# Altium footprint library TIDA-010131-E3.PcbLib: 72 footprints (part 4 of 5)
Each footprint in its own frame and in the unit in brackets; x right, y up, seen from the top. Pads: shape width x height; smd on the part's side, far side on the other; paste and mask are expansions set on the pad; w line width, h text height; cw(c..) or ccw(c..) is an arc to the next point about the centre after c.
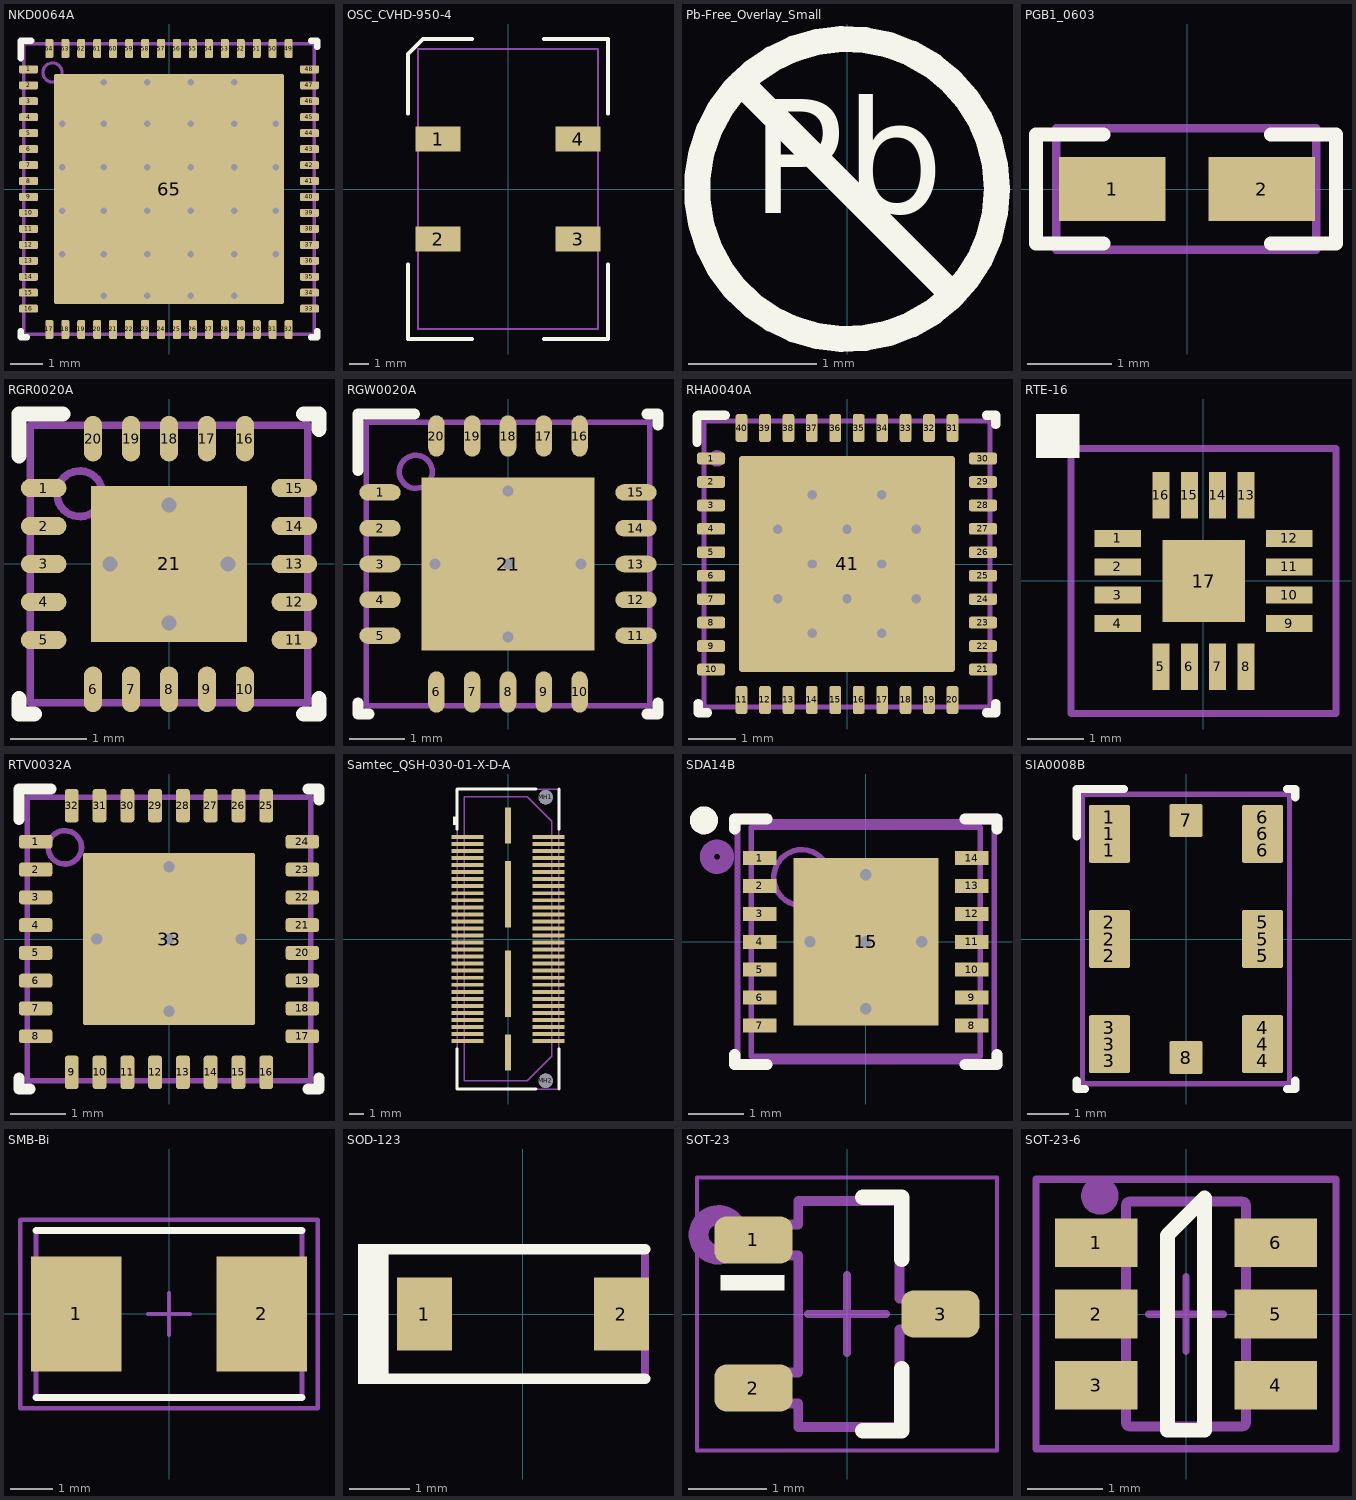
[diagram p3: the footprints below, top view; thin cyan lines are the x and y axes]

## NKD0064A [mm] "QFN, 64-Leads, Body 9x9mm, Pitch 0.5mm"
height 0.8
pads (65):
  rrect40% 0.6x0.25 smd: 1(-4.4,3.75) 2(-4.4,3.25) 3(-4.4,2.75) 4(-4.4,2.25) 5(-4.4,1.75) 6(-4.4,1.25) 7(-4.4,0.75) 8(-4.4,0.25) 9(-4.4,-0.25) 10(-4.4,-0.75) 11(-4.4,-1.25) 12(-4.4,-1.75) 13(-4.4,-2.25) 14(-4.4,-2.75) 15(-4.4,-3.25) 16(-4.4,-3.75) 33(4.4,-3.75) 34(4.4,-3.25) 35(4.4,-2.75) 36(4.4,-2.25) 37(4.4,-1.75) 38(4.4,-1.25) 39(4.4,-0.75) 40(4.4,-0.25) 41(4.4,0.25) 42(4.4,0.75) 43(4.4,1.25) 44(4.4,1.75) 45(4.4,2.25) 46(4.4,2.75) 47(4.4,3.25) 48(4.4,3.75)
  rrect40% 0.25x0.6 smd: 17(-3.75,-4.4) 18(-3.25,-4.4) 19(-2.75,-4.4) 20(-2.25,-4.4) 21(-1.75,-4.4) 22(-1.25,-4.4) 23(-0.75,-4.4) 24(-0.25,-4.4) 25(0.25,-4.4) 26(0.75,-4.4) 27(1.25,-4.4) 28(1.75,-4.4) 29(2.25,-4.4) 30(2.75,-4.4) 31(3.25,-4.4) 32(3.75,-4.4) 49(3.75,4.4) 50(3.25,4.4) 51(2.75,4.4) 52(2.25,4.4) 53(1.75,4.4) 54(1.25,4.4) 55(0.75,4.4) 56(0.25,4.4) 57(-0.25,4.4) 58(-0.75,4.4) 59(-1.25,4.4) 60(-1.75,4.4) 61(-2.25,4.4) 62(-2.75,4.4) 63(-3.25,4.4) 64(-3.75,4.4)
  rrect1% 7.2x7.2 smd paste-3.6: 65(0,0)
via 0.68,-3.35 diameter 0.5 hole 0.2
via -0.68,-3.35 diameter 0.5 hole 0.2
via 3.35,0.68 diameter 0.5 hole 0.2
via 3.35,2.04 diameter 0.5 hole 0.2
via -3.35,0.68 diameter 0.5 hole 0.2
via -3.35,2.04 diameter 0.5 hole 0.2
via -3.35,-0.68 diameter 0.5 hole 0.2
via -3.35,-2.04 diameter 0.5 hole 0.2
via 3.35,-2.04 diameter 0.5 hole 0.2
via 3.35,-0.68 diameter 0.5 hole 0.2
via -2.04,-3.35 diameter 0.5 hole 0.2
via 2.04,-3.35 diameter 0.5 hole 0.2
via 2.04,3.35 diameter 0.5 hole 0.2
via 0.68,3.35 diameter 0.5 hole 0.2
via -0.68,3.35 diameter 0.5 hole 0.2
via -2.04,3.35 diameter 0.5 hole 0.2
via 2.04,2.04 diameter 0.5 hole 0.2
via 0.68,2.04 diameter 0.5 hole 0.2
via -0.68,2.04 diameter 0.5 hole 0.2
via -2.04,2.04 diameter 0.5 hole 0.2
via 2.04,-2.04 diameter 0.5 hole 0.2
via 0.68,-2.04 diameter 0.5 hole 0.2
via -0.68,-2.04 diameter 0.5 hole 0.2
via -2.04,-2.04 diameter 0.5 hole 0.2
via -2.04,-0.68 diameter 0.5 hole 0.2
via 2.04,-0.68 diameter 0.5 hole 0.2
via 2.04,0.68 diameter 0.5 hole 0.2
via -2.04,0.68 diameter 0.5 hole 0.2
via 0.68,-0.68 diameter 0.5 hole 0.2
via -0.68,-0.68 diameter 0.5 hole 0.2
via -0.68,0.68 diameter 0.5 hole 0.2
via 0.68,0.68 diameter 0.5 hole 0.2
Top Overlay:
  lines w0.2: -4.65,-4.45 -4.65,-4.65 -4.45,-4.65 ; -4.65,4.1 -4.65,4.65 -4.32,4.65 ; 4.45,-4.65 4.65,-4.65 4.65,-4.45 ; 4.45,4.65 4.65,4.65 4.65,4.45
Top Paste:
  rectangle: -3.3,-3.3 -2.14,-2.14
  rectangle: -1.94,-3.3 -0.78,-2.14
  rectangle: -0.58,-3.3 0.58,-2.14
  rectangle: 0.78,-3.3 1.94,-2.14
  rectangle: 2.14,-3.3 3.3,-2.14
  rectangle: 2.14,-1.94 3.3,-0.78
  rectangle: 0.78,-1.94 1.94,-0.78
  rectangle: -0.58,-1.94 0.58,-0.78
  rectangle: -1.94,-1.94 -0.78,-0.78
  rectangle: -3.3,-1.94 -2.14,-0.78
  rectangle: -3.3,-0.58 -2.14,0.58
  rectangle: -1.94,-0.58 -0.78,0.58
  rectangle: -1.94,0.78 -0.78,1.94
  rectangle: -3.3,0.78 -2.14,1.94
  rectangle: -3.3,2.14 -2.14,3.3
  rectangle: -1.94,2.14 -0.78,3.3
  rectangle: -0.58,2.14 0.58,3.3
  rectangle: -0.58,0.78 0.58,1.94
  rectangle: 2.14,0.78 3.3,1.94
  rectangle: 2.14,2.14 3.3,3.3
  rectangle: 0.78,2.14 1.94,3.3
  rectangle: 0.78,0.78 1.94,1.94
  rectangle: 2.14,-0.58 3.3,0.58
  rectangle: 0.78,-0.58 1.94,0.58
  rectangle: -0.58,-0.58 0.58,0.58
Mechanical 5:
  circle w0.1: c-3.65,3.65 r0.3
  lines w0.1: -4.55,-4.55 4.55,-4.55 4.55,4.55 -4.55,4.55 -4.55,-4.55
  text ".Designator" at -0.047,0.001 h0.64
3D body: height 0.8, standoff 0, extent -4.549,-4.549 4.549,4.549
3D body: height 0.81, standoff 0.5, extent -3.949,3.351 -3.351,3.949

## OSC_CVHD-950-4 [mil] "Crystek recommended land pattern 2011-02-22 Rev H"
height 210
pads (4):
  rect 90x50 smd: 1(-140,100) 2(-140,-100) 3(140,-100) 4(140,100)
Top Overlay:
  lines w7.87: -200,-151.18 -200,-300 -71.73,-300 ; -200,151.18 -200,270 -170,300 -71.73,300 ; 71.73,-300 200,-300 200,-151.18 ; 71.73,300 200,300 200,151.18
Mechanical 5:
  lines w4: -180,-280 180,-280 180,280 -180,280 -180,-280
  text ".Designator" at 5.45,-44.75 h25
3D body "Crystek_CVHD-950.stp": height 209.06, standoff -0.39, extent -179.84,-279.53 180,279.53

## Pb-Free_Overlay_Small [mm]
height 9.53
Top Overlay:
  circle w0.203: c0,0 r1.168
  lines w0.203: -0.826,0.826 0.826,-0.826
  text "Pb" at -0.752,-0.48 h1.52

## PGB1_0603 [mm] "Littelfuse"
height 0.36
pads (2):
  rect 1.27x0.76 smd: 1(-0.89,0) 2(0.89,0)
Top Overlay:
  lines w0.17: -1,-0.65 -1.8,-0.65 -1.8,0.65 -1,0.65 ; 1,-0.65 1.775,-0.65 1.775,-0.15 1.775,0.575 1.775,0.65 1,0.65
Mechanical 5:
  lines w0.1: -1.56,-0.725 -1.56,0.725 1.54,0.725 1.54,-0.725 -1.56,-0.725
  text ".Designator" at -1.27,-0.37 h0.64
3D body: height 0.18, standoff 0, extent -0.859,-0.444 -0.521,0.444
3D body: height 0.18, standoff 0, extent 0.521,-0.444 0.859,0.444
3D body: height 0.18, standoff 0, extent -0.519,-0.444 0.519,0.444
3D body: height 0.36, standoff 0.18, extent -0.519,-0.444 0.519,0.444

## RGR0020A [mm] "QFN, 20-Leads, Body 3.5x3.5mm, Pitch 0.5mm, Thermal Pad 2.05x2.05mm, TI Recommended"
height 1
pads (21):
  oval 0.6x0.24 smd: 1(-1.65,1) 2(-1.65,0.5) 3(-1.65,0) 4(-1.65,-0.5) 5(-1.65,-1) 11(1.65,-1) 12(1.65,-0.5) 13(1.65,0) 14(1.65,0.5) 15(1.65,1)
  oval 0.24x0.6 smd: 6(-1,-1.65) 7(-0.5,-1.65) 8(0,-1.65) 9(0.5,-1.65) 10(1,-1.65) 16(1,1.65) 17(0.5,1.65) 18(0,1.65) 19(-0.5,1.65) 20(-1,1.65)
  rect 2.05x2.05 smd paste-1.025: 21(0,0)
via 0,-0.775 diameter 0.5 hole 0.2
via 0,0.775 diameter 0.5 hole 0.2
via -0.775,0 diameter 0.5 hole 0.2
via 0.775,0 diameter 0.5 hole 0.2
Top Overlay:
  lines w0.2: -1.975,-1.775 -1.975,-1.975 -1.775,-1.975 ; -1.975,1.425 -1.975,1.975 -1.4,1.975 ; 1.775,-1.975 1.975,-1.975 1.975,-1.775 ; 1.775,1.975 1.975,1.975 1.975,1.775
Top Paste:
  rectangle: 0.1,0.1 1.017,1.017
  region: -0.1,1.017 -1.017,1.017 -1.017,0.1 -0.1,0.1
  region: -0.1,-0.1 -1.017,-0.1 -1.017,-1.017 -0.1,-1.017
  rectangle: 0.1,-1.017 1.017,-0.1
Mechanical 5:
  circle w0.1: c-1.175,0.925 r0.3
  lines w0.1: -1.825,-1.825 -1.825,1.825 1.825,1.825 1.825,-1.825 -1.825,-1.825
  text ".Designator" at -0.858,-0.458 h0.64
3D body: height 1, standoff 0, extent -1.825,-1.825 1.825,1.825
3D body: height 1.01, standoff 0.5, extent -1.474,0.626 -0.876,1.224

## RGW0020A [mm] "QFN, 20-Leads, Body 5x5mm, Pitch 0.65mm, Thermal Pad 3.15x3.15mm, TI Recommended"
height 1
pads (21):
  oval 0.75x0.3 smd: 1(-2.325,1.3) 2(-2.325,0.65) 3(-2.325,0) 4(-2.325,-0.65) 5(-2.325,-1.3) 11(2.325,-1.3) 12(2.325,-0.65) 13(2.325,0) 14(2.325,0.65) 15(2.325,1.3)
  oval 0.3x0.75 smd: 6(-1.3,-2.325) 7(-0.65,-2.325) 8(0,-2.325) 9(0.65,-2.325) 10(1.3,-2.325) 16(1.3,2.325) 17(0.65,2.325) 18(0,2.325) 19(-0.65,2.325) 20(-1.3,2.325)
  rect 3.15x3.15 smd paste-1.575: 21(0,0)
via 0,1.325 diameter 0.5 hole 0.2
via -1.325,0 diameter 0.5 hole 0.2
via 0,0 diameter 0.5 hole 0.2
via 1.325,0 diameter 0.5 hole 0.2
via 0,-1.325 diameter 0.5 hole 0.2
Top Overlay:
  lines w0.2: -2.725,-2.525 -2.725,-2.725 -2.525,-2.725 ; -2.725,1.7 -2.725,2.725 -1.7,2.725 ; 2.525,-2.725 2.725,-2.725 2.725,-2.525 ; 2.525,2.725 2.725,2.725 2.725,2.525
Top Paste:
  rectangle: 0.1,0.1 1.468,1.468
  region: -0.1,1.468 -1.468,1.468 -1.468,0.1 -0.1,0.1
  region: -0.1,-0.1 -1.468,-0.1 -1.468,-1.468 -0.1,-1.468
  rectangle: 0.1,-1.468 1.468,-0.1
Mechanical 5:
  circle w0.1: c-1.675,1.675 r0.3
  lines w0.1: -2.575,-2.575 -2.575,2.575 2.575,2.575 2.575,-2.575 -2.575,-2.575
  text ".Designator" at -0.591,-0.29 h0.64
3D body: height 1, standoff 0, extent -2.575,-2.575 2.575,2.575
3D body: height 1.01, standoff 0.5, extent -1.974,1.376 -1.376,1.974

## RHA0040A [mm] "QFN, 40-Leads, Body 6x6mm, Pitch 0.5mm, Thermal Pad 4.6x4.6mm, TI Recommended"
height 1
pads (41):
  rrect40% 0.6x0.25 smd: 1(-2.9,2.25) 2(-2.9,1.75) 3(-2.9,1.25) 4(-2.9,0.75) 5(-2.9,0.25) 6(-2.9,-0.25) 7(-2.9,-0.75) 8(-2.9,-1.25) 9(-2.9,-1.75) 10(-2.9,-2.25) 21(2.9,-2.25) 22(2.9,-1.75) 23(2.9,-1.25) 24(2.9,-0.75) 25(2.9,-0.25) 26(2.9,0.25) 27(2.9,0.75) 28(2.9,1.25) 29(2.9,1.75) 30(2.9,2.25)
  rrect40% 0.25x0.6 smd: 11(-2.25,-2.9) 12(-1.75,-2.9) 13(-1.25,-2.9) 14(-0.75,-2.9) 15(-0.25,-2.9) 16(0.25,-2.9) 17(0.75,-2.9) 18(1.25,-2.9) 19(1.75,-2.9) 20(2.25,-2.9) 31(2.25,2.9) 32(1.75,2.9) 33(1.25,2.9) 34(0.75,2.9) 35(0.25,2.9) 36(-0.25,2.9) 37(-0.75,2.9) 38(-1.25,2.9) 39(-1.75,2.9) 40(-2.25,2.9)
  rrect2% 4.6x4.6 smd paste-2.3: 41(0,0)
via 0,0.74 diameter 0.5 hole 0.2
via -0.74,-1.48 diameter 0.5 hole 0.2
via 0.74,-1.48 diameter 0.5 hole 0.2
via -0.74,1.48 diameter 0.5 hole 0.2
via 0.74,0 diameter 0.5 hole 0.2
via -1.48,0.74 diameter 0.5 hole 0.2
via 1.48,0.74 diameter 0.5 hole 0.2
via 0.74,1.48 diameter 0.5 hole 0.2
via 1.48,-0.74 diameter 0.5 hole 0.2
via -0.74,0 diameter 0.5 hole 0.2
via -1.48,-0.74 diameter 0.5 hole 0.2
via 0,-0.74 diameter 0.5 hole 0.2
Top Overlay:
  lines w0.2: -3.2,2.6 -3.2,3.15 ; -3.175,-2.975 -3.175,-3.175 -2.975,-3.175 ; -3.175,3.175 -2.6,3.175 ; 2.975,-3.175 3.175,-3.175 3.175,-2.975 ; 2.975,3.175 3.175,3.175 3.175,2.975
Top Paste:
  region: -0.84,-0.84 -2.12,-0.84 -2.12,-2.12 -0.84,-2.12
  rectangle: 0.84,-2.12 2.12,-0.84
  rectangle: -0.64,-2.12 0.64,-0.84
  rectangle: -0.64,0.84 0.64,2.12
  rectangle: 0.84,0.84 2.12,2.12
  region: -0.84,2.12 -2.12,2.12 -2.12,0.84 -0.84,0.84
  region: -0.84,0.64 -2.12,0.64 -2.12,-0.64 -0.84,-0.64
  rectangle: 0.84,-0.64 2.12,0.64
  rectangle: -0.64,-0.64 0.64,0.64
Mechanical 5:
  circle w0.1: c-2.774,2.252 r0.127
  lines w0.1: -3.05,-3.05 -3.05,3.05 3.05,3.05 3.05,-3.05 -3.05,-3.05
  text ".Designator" at 0.606,0.295 h0.64
3D body "RHA0040A.stp": height 1, standoff 0, extent -3,-3 3,3

## RTE-16 [mil]
height 375.2
pads (17):
  rect 32.24x11.8 smd mask+1: 1(-59.45,29.55) 2(-59.45,9.85) 3(-59.45,-9.85) 4(-59.45,-29.55) 9(59.55,-29.55) 10(59.55,-9.85) 11(59.55,9.85) 12(59.55,29.55)
  rect 11.8x32.24 smd mask+1: 5(-29.5,-59.5) 6(-9.8,-59.5) 7(9.9,-59.5) 8(29.6,-59.5) 13(29.6,59.5) 14(9.9,59.5) 15(-9.8,59.5) 16(-29.5,59.5)
  rect 57.09x57.09 smd mask+1.18: 17(0.15,-0.05)
Top Overlay:
  region: -116.19,85.59 -86.19,85.59 -86.19,115.59 -116.19,115.59
Mechanical 5:
  lines w5: -92,-92 -92,92 92,92 92,-92 -92,-92
  text ".Designator" at 6,-29 h25
  text "*" at -82.68,51.18 h25

## RTV0032A [mm] "QFN, 32-Leads, Body 5x5mm, Pitch 0.5mm"
height 0.8
pads (33):
  rrect40% 0.6x0.25 smd: 1(-2.4,1.75) 2(-2.4,1.25) 3(-2.4,0.75) 4(-2.4,0.25) 5(-2.4,-0.25) 6(-2.4,-0.75) 7(-2.4,-1.25) 8(-2.4,-1.75) 17(2.4,-1.75) 18(2.4,-1.25) 19(2.4,-0.75) 20(2.4,-0.25) 21(2.4,0.25) 22(2.4,0.75) 23(2.4,1.25) 24(2.4,1.75)
  rrect40% 0.25x0.6 smd: 9(-1.75,-2.4) 10(-1.25,-2.4) 11(-0.75,-2.4) 12(-0.25,-2.4) 13(0.25,-2.4) 14(0.75,-2.4) 15(1.25,-2.4) 16(1.75,-2.4) 25(1.75,2.4) 26(1.25,2.4) 27(0.75,2.4) 28(0.25,2.4) 29(-0.25,2.4) 30(-0.75,2.4) 31(-1.25,2.4) 32(-1.75,2.4)
  rrect3% 3.1x3.1 smd paste-1.55: 33(0,0)
via 0,-1.3 diameter 0.5 hole 0.2
via 1.3,0 diameter 0.5 hole 0.2
via 0,0 diameter 0.5 hole 0.2
via -1.3,0 diameter 0.5 hole 0.2
via 0,1.3 diameter 0.5 hole 0.2
Top Overlay:
  lines w0.2: -2.7,-2.5 -2.7,-2.7 -2.5,-2.7 ; -2.7,2.15 -2.7,2.7 -2.125,2.7 ; 2.5,-2.7 2.7,-2.7 2.7,-2.5 ; 2.5,2.7 2.7,2.7 2.7,2.5
Top Paste:
  rectangle: 0.1,-1.4 1.4,-0.1
  region: -0.1,-0.1 -1.4,-0.1 -1.4,-1.4 -0.1,-1.4
  region: -0.1,1.4 -1.4,1.4 -1.4,0.1 -0.1,0.1
  rectangle: 0.1,0.1 1.4,1.4
Mechanical 5:
  circle w0.1: c-1.875,1.65 r0.3
  lines w0.1: -2.55,-2.55 2.55,-2.55 2.55,2.55 -2.55,2.55 -2.55,-2.55
  text ".Designator" at -1.524,-0.508 h0.64
3D body: height 0.8, standoff 0, extent -2.55,-2.55 2.55,2.55
3D body: height 0.81, standoff 0.5, extent -2.174,1.351 -1.576,1.949

## Samtec_QSH-030-01-X-D-A [mm] "Receptacle, 0.5 mm, 30x2, TH"
height 3.327
pads (66):
  rect 2.27x0.279 smd: 1(-2.865,7.25) 2(2.865,7.25) 3(-2.865,6.75) 4(2.865,6.75) 5(-2.865,6.25) 6(2.865,6.25) 7(-2.865,5.75) 8(2.865,5.75) 9(-2.865,5.25) 10(2.865,5.25) 11(-2.865,4.75) 12(2.865,4.75) 13(-2.865,4.25) 14(2.865,4.25) 15(-2.865,3.75) 16(2.865,3.75) 17(-2.865,3.25) 18(2.865,3.25) 19(-2.865,2.75) 20(2.865,2.75) 21(-2.865,2.25) 22(2.865,2.25) 23(-2.865,1.75) 24(2.865,1.75) 25(-2.865,1.25) 26(2.865,1.25) 27(-2.865,0.75) 28(2.865,0.75) 29(-2.865,0.25) 30(2.865,0.25) 31(-2.865,-0.25) 32(2.865,-0.25) 33(-2.865,-0.75) 34(2.865,-0.75) 35(-2.865,-1.25) 36(2.865,-1.25) 37(-2.865,-1.75) 38(2.865,-1.75) 39(-2.865,-2.25) 40(2.865,-2.25) 41(-2.865,-2.75) 42(2.865,-2.75) 43(-2.865,-3.25) 44(2.865,-3.25) 45(-2.865,-3.75) 46(2.865,-3.75) 47(-2.865,-4.25) 48(2.865,-4.25) 49(-2.865,-4.75) 50(2.865,-4.75) 51(-2.865,-5.25) 52(2.865,-5.25) 53(-2.865,-5.75) 54(2.865,-5.75) 55(-2.865,-6.25) 56(2.865,-6.25) 57(-2.865,-6.75) 58(2.865,-6.75) 59(-2.865,-7.25) 60(2.865,-7.25)
  round 1.02 hole 1.02 unplated mask+0.254: MH1(2.67,10.065)
  round 1.02 hole 1.02 unplated paste+0 mask+0.254: MH2(2.67,-10.065)
  rect 0.43x2.54 smd: MP1(0,8.065) MP4(0,-8.065)
  rect 0.43x4.7 smd: MP2(0,3.175) MP3(0,-3.175)
Top Overlay:
  rectangle: -3.9,8.1 -3.62,8.7
  lines w0.2: -3.62,-7.789 -3.62,-10.655 2,-10.655 ; -3.62,7.789 -3.62,10.655 2,10.655 ; 3.62,-10.655 3.62,-7.789 ; 3.62,7.789 3.62,10.655
Mechanical 5:
  drawing of 190 lines, arcs and shapes, not listed
  text ".Designator" at -1.524,-0.508 h0.64
3D body "Samtec-QSH-030-01-L-D-A.stp": height 3.25, standoff -0.75, extent -3.746,-10.636 3.747,10.674

## SDA14B [mm] "SON, 14-Leads, Body 4x4mm, Pitch 0.5mm, NSC Recommended"
height 0.8
pads (15):
  rect 0.6x0.25 smd paste-0.125 mask+0.051: 1(-1.9,1.5) 2(-1.9,1) 3(-1.9,0.5) 4(-1.9,0) 5(-1.9,-0.5) 6(-1.9,-1) 7(-1.9,-1.5) 8(1.9,-1.5) 9(1.9,-1) 10(1.9,-0.5) 11(1.9,0) 12(1.9,0.5) 13(1.9,1) 14(1.9,1.5)
  rect 2.6x3 smd paste-1.3 mask+0.051: 15(0,0)
via 0,0 diameter 0.406 hole 0.203
via 1,0 diameter 0.406 hole 0.203
via -1,0 diameter 0.406 hole 0.203
via 0,-1.2 diameter 0.406 hole 0.203
via 0,1.2 diameter 0.406 hole 0.203
Top Overlay:
  circle w0.25: c-2.9,2.175 r0.125
  lines w0.2: -2.35,-2.025 -2.35,-2.2 -1.775,-2.2 ; -2.35,2.025 -2.35,2.2 -1.775,2.2 ; 1.775,-2.2 2.35,-2.2 2.35,-2.025 ; 1.775,2.2 2.35,2.2 2.35,2.025
Top Paste:
  region: 1.2,1.4 0.1,1.4 0.1,0.1 1.2,0.1
  region: 1.2,-0.1 0.1,-0.1 0.1,-1.4 1.2,-1.4
  rectangle: -1.2,-1.4 -0.1,-0.1
  rectangle: -1.2,0.1 -0.1,1.4
  region: -2.4,-1.375 -2.4,-1.625 -1.7,-1.625 -1.7,-1.375
  region: -2.4,-0.875 -2.4,-1.125 -1.7,-1.125 -1.7,-0.875
  region: -2.4,-0.375 -2.4,-0.625 -1.7,-0.625 -1.7,-0.375
  region: -2.4,0.125 -2.4,-0.125 -1.7,-0.125 -1.7,0.125
  region: -2.4,1.125 -2.4,0.875 -1.7,0.875 -1.7,1.125
  region: -2.4,1.625 -2.4,1.375 -1.7,1.375 -1.7,1.625
  region: 1.7,1.625 1.7,1.375 2.4,1.375 2.4,1.625
  region: 1.7,1.125 1.7,0.875 2.4,0.875 2.4,1.125
  region: 1.7,0.625 1.7,0.375 2.4,0.375 2.4,0.625
  region: 1.7,0.125 1.7,-0.125 2.4,-0.125 2.4,0.125
  region: 1.7,-0.375 1.7,-0.625 2.4,-0.625 2.4,-0.375
  region: 1.7,-0.875 1.7,-1.125 2.4,-1.125 2.4,-0.875
  region: 1.7,-1.375 1.7,-1.625 2.4,-1.625 2.4,-1.375
  region: -2.4,0.625 -2.4,0.375 -1.7,0.375 -1.7,0.625
Mechanical 5:
  circle w0.254: c-2.667,1.524 r0.18
  lines w0.2: -2.35,-2.025 -2.35,-2.2 -1.775,-2.2 ; -2.35,2.025 -2.35,2.2 -1.775,2.2 ; 1.775,-2.2 2.35,-2.2 2.35,-2.025 ; 1.775,2.2 2.35,2.2 2.35,2.025
  text ".Designator" at -0.512,-0.039 h0.51
Mechanical 13:
  circle w0.1: c-1.15,1.15 r0.5
  lines w0.1: -2.05,-2.05 -2.05,2.05 2.05,2.05 2.05,-2.05 -2.05,-2.05
Mechanical 15:
  lines w0.1: -0.5,0 0.5,0 ; 0,-0.5 0,0.5 ; -2.3,-2.15 -2.3,2.15 2.3,2.15 2.3,-2.15 -2.3,-2.15
3D body: height 0.8, standoff 0, extent -2.049,-2.049 2.049,2.049

## SIA0008B [mm] "SIP 8-Leads, Body 5x7mm"
height 1.1
pads (20):
  rrect50% 1x0.6 on Top Paste: 1(-1.85,2.14) 1(-1.85,2.94) 2(-1.85,-0.4) 2(-1.85,0.4) 3(-1.85,-2.94) 3(-1.85,-2.14) 4(1.85,-2.94) 4(1.85,-2.14) 5(1.85,-0.4) 5(1.85,0.4) 6(1.85,2.14) 6(1.85,2.94)
  rrect10% 1x1.4 smd paste-0.5: 1(-1.85,2.54) 2(-1.85,0) 3(-1.85,-2.54) 4(1.85,-2.54) 5(1.85,0) 6(1.85,2.54)
  rrect12% 0.8x0.8 smd: 7(0,2.865) 8(0,-2.865)
Top Overlay:
  lines w0.2: -2.64,-3.425 -2.64,-3.625 -2.44,-3.625 ; -2.64,2.485 -2.64,3.625 -1.5,3.625 ; 2.44,-3.625 2.64,-3.625 2.64,-3.425 ; 2.44,3.625 2.64,3.625 2.64,3.425
Mechanical 5:
  circle w0.1: c-1.84,2.54 r0.25
  lines w0.127: -2.5,-3.5 -2.5,3.5 2.5,3.5 2.5,-3.5 -2.5,-3.5
  text ".Designator" at 0.511,0.186 h0.64
3D body: height 1.1, standoff 0, extent -2.564,-3.564 2.564,3.564
3D body: height 1.13, standoff 0, extent -2.156,2.224 -1.525,2.856

## SMB-Bi [mm] "Molded Diode, 2-Leads, Body 5.4x3.6mm, IPC Medium Density, based on OnSemi component dimensions"
height 2.65
pads (2):
  rect 2.159x2.743 smd: 1(-2.21,0) 2(2.21,0)
Top Overlay:
  lines w0.178: -3.175,-1.994 3.175,-1.994 ; -3.175,1.994 3.175,1.994
Mechanical 5:
  lines w0.127: -3.175,-1.994 -3.175,-1.765 -3.175,1.765 -3.175,1.994 3.175,1.994 3.175,1.765 3.175,-1.765 3.175,-1.994 -3.175,-1.994
  text ".Designator" at 0.249,-0.504 h0.64
Mechanical 15:
  lines w0.1: -0.5,0 0.5,0 ; 0,-0.5 0,0.5 ; -3.55,-2.25 3.55,-2.25 3.55,2.25 -3.55,2.25 -3.55,-2.25
3D body "SMB-Bi.stp": height 2.26, standoff 0.01, extent -2.65,-1.85 2.65,1.85

## SOD-123 [mm] "On Semi recommended land pattern"
height 1.35
pads (2):
  rect 0.915x1.22 smd: 1(-1.637,0) 2(1.637,0)
Top Overlay:
  rectangle: -2.743,-1.168 -2.235,1.168
  lines w0.178: -2.413,-1.079 2.032,-1.079 ; -2.413,1.079 2.032,1.079
Mechanical 5:
  rectangle: -2.743,-1.168 -2.235,1.168
  lines w0.127: -2.413,-1.079 2.032,-1.079 2.032,1.079 -2.413,1.079
  text ".Designator" at -0.722,0.389 h0.64
3D body "SOD-123.stp": height 1.35, standoff 0, extent -1.932,-0.9 1.932,0.9

## SOT-23 [mm] "SOT23, 3-Leads, Body 2.9x1.3mm, Pitch 0.95mm, Lead Span 2.5mm, IPC Medium Density"
height 1.1
pads (3):
  rrect50% 1x0.6 smd: 1(-1.2,0.95) 2(-1.2,-0.95) 3(1.2,0)
Top Overlay:
  rectangle: -1.625,0.3 -0.8,0.5
  lines w0.2: 0.2,-1.5 0.7,-1.5 0.7,-0.7 ; 0.2,1.5 0.7,1.5 0.7,0.7
Mechanical 5:
  circle w0.254: c-1.651,1.016 r0.254
  lines w0.127: -1.16,-1.15 -0.625,-1.15 -0.625,-1.45 0.675,-1.45 0.675,-0.2 1.21,-0.2 1.21,0.2 0.675,0.2 0.675,1.45 -0.625,1.45 -0.625,1.15 -1.16,1.15 -1.16,0.75 -0.625,0.75 -0.625,-0.75 -1.16,-0.75 -1.16,-1.15
  text ".Designator" at 0.485,0.269 h0.51
Mechanical 15:
  lines w0.05: -1.925,-1.75 -1.925,1.75 1.925,1.75 1.925,-1.75 -1.925,-1.75
  lines w0.1: -0.5,0 0.5,0 ; 0,-0.5 0,0.5
3D body "SW3dPS-sot-3p290x130ll237h100.STEP": height 1, standoff 0, extent -1.16,-1.45 1.21,1.45

## SOT-23-6 [mm] "SOT23, 6-Leads, Body 3.0x1.7mm, Pitch 0.95mm, Lead Span 2.9mm, IPC Medium Density"
height 1
pads (6):
  rect 1.1x0.65 smd: 1(-1.2,0.95) 2(-1.2,0) 3(-1.2,-0.95) 4(1.2,-0.95) 5(1.2,0) 6(1.2,0.95)
Top Overlay:
  lines w0.2: -0.25,-1.55 0.25,-1.55 0.25,1.55 -0.25,1.05 -0.25,-1.55
Mechanical 5:
  circle w0.25: c-1.15,1.575 r0.125
  lines w0.127: -0.8,-1.45 ccw(c-0.75,-1.45) -0.75,-1.5 ; -0.8,-1.45 -0.8,-1.2 ; -0.8,-1.45 -0.8,-1.45 ; -0.8,-1.2 -0.812,-1.2 -1.109,-1.2 -1.166,-1.2 -1.265,-1.2 -1.5,-1.2 -1.5,-0.7 -1.265,-0.7 -1.166,-0.7 -1.109,-0.7 -0.812,-0.7 -0.8,-0.7 ; -0.8,-1.2 -0.8,-0.7 ; -0.8,-0.7 -0.8,-0.25 ; -0.8,-0.25 -0.812,-0.25 -1.109,-0.25 -1.166,-0.25 -1.265,-0.25 -1.5,-0.25 -1.5,0.25 -1.265,0.25 -1.166,0.25 -1.109,0.25 -0.812,0.25 -0.8,0.25 ; -0.8,-0.25 -0.8,0.25 ; -0.8,0.25 -0.8,0.7 ; -0.8,0.7 -0.812,0.7 -1.109,0.7 -1.166,0.7 -1.265,0.7 -1.5,0.7 -1.5,1.2 -1.265,1.2 -1.166,1.2 -1.109,1.2 -0.812,1.2 -0.8,1.2 ; -0.8,0.7 -0.8,1.2 ; -0.8,1.2 -0.8,1.45 ; -0.8,1.45 cw(c-0.75,1.45) -0.75,1.5 ; -0.8,1.45 -0.8,1.45 ; -0.75,-1.5 -0.75,-1.5 ; -0.75,-1.5 0.75,-1.5 ; -0.75,1.5 0.75,1.5 ; -0.75,1.5 -0.75,1.5 ; 0.75,-1.5 ccw(c0.75,-1.45) 0.8,-1.45 ; 0.75,-1.5 0.75,-1.5 ; 0.75,1.5 cw(c0.75,1.45) 0.8,1.45 ; 0.75,1.5 0.75,1.5 ; 0.8,-1.45 0.8,-1.2 ; 0.8,-1.45 0.8,-1.45 ; 0.8,-1.2 0.8,-0.7 ; 0.8,-1.2 0.812,-1.2 1.109,-1.2 1.166,-1.2 1.265,-1.2 1.5,-1.2 1.5,-0.7 1.265,-0.7 1.166,-0.7 1.109,-0.7 0.812,-0.7 0.8,-0.7 ; 0.8,-0.7 0.8,-0.25 ; 0.8,-0.25 0.812,-0.25 1.109,-0.25 1.166,-0.25 1.265,-0.25 1.5,-0.25 1.5,0.25 1.265,0.25 1.166,0.25 1.109,0.25 0.812,0.25 0.8,0.25 ; 0.8,-0.25 0.8,0.25 ; 0.8,0.25 0.8,0.7 ; 0.8,0.7 0.8,1.2 ; 0.8,0.7 0.812,0.7 1.109,0.7 1.166,0.7 1.265,0.7 1.5,0.7 1.5,1.2 1.265,1.2 1.166,1.2 1.109,1.2 0.812,1.2 0.8,1.2 ; 0.8,1.2 0.8,1.45 ; 0.8,1.45 0.8,1.45
  text ".Designator" at -0.356,0.589 h0.64
Mechanical 15:
  lines w0.1: -0.5,0 0.5,0 ; 0,-0.5 0,0.5 ; -2,-1.8 -2,1.8 2,1.8 2,-1.8 -2,-1.8
3D body "SOT23-6.stp": height 1.3, standoff 0, extent -1.5,-1.5 1.5,1.5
